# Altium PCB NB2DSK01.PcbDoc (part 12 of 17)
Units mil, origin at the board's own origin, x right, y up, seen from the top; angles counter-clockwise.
Board outline 11815 x 6500.03 mil, 8 copper layers (Top Layer, MidLayer1, MidLayer2, GND, PWR, MidLayer3, MidLayer4, Bottom Layer), stack 74.62 mil thick; 798 components, 1002 nets, 3927 pads, 3182 vias.
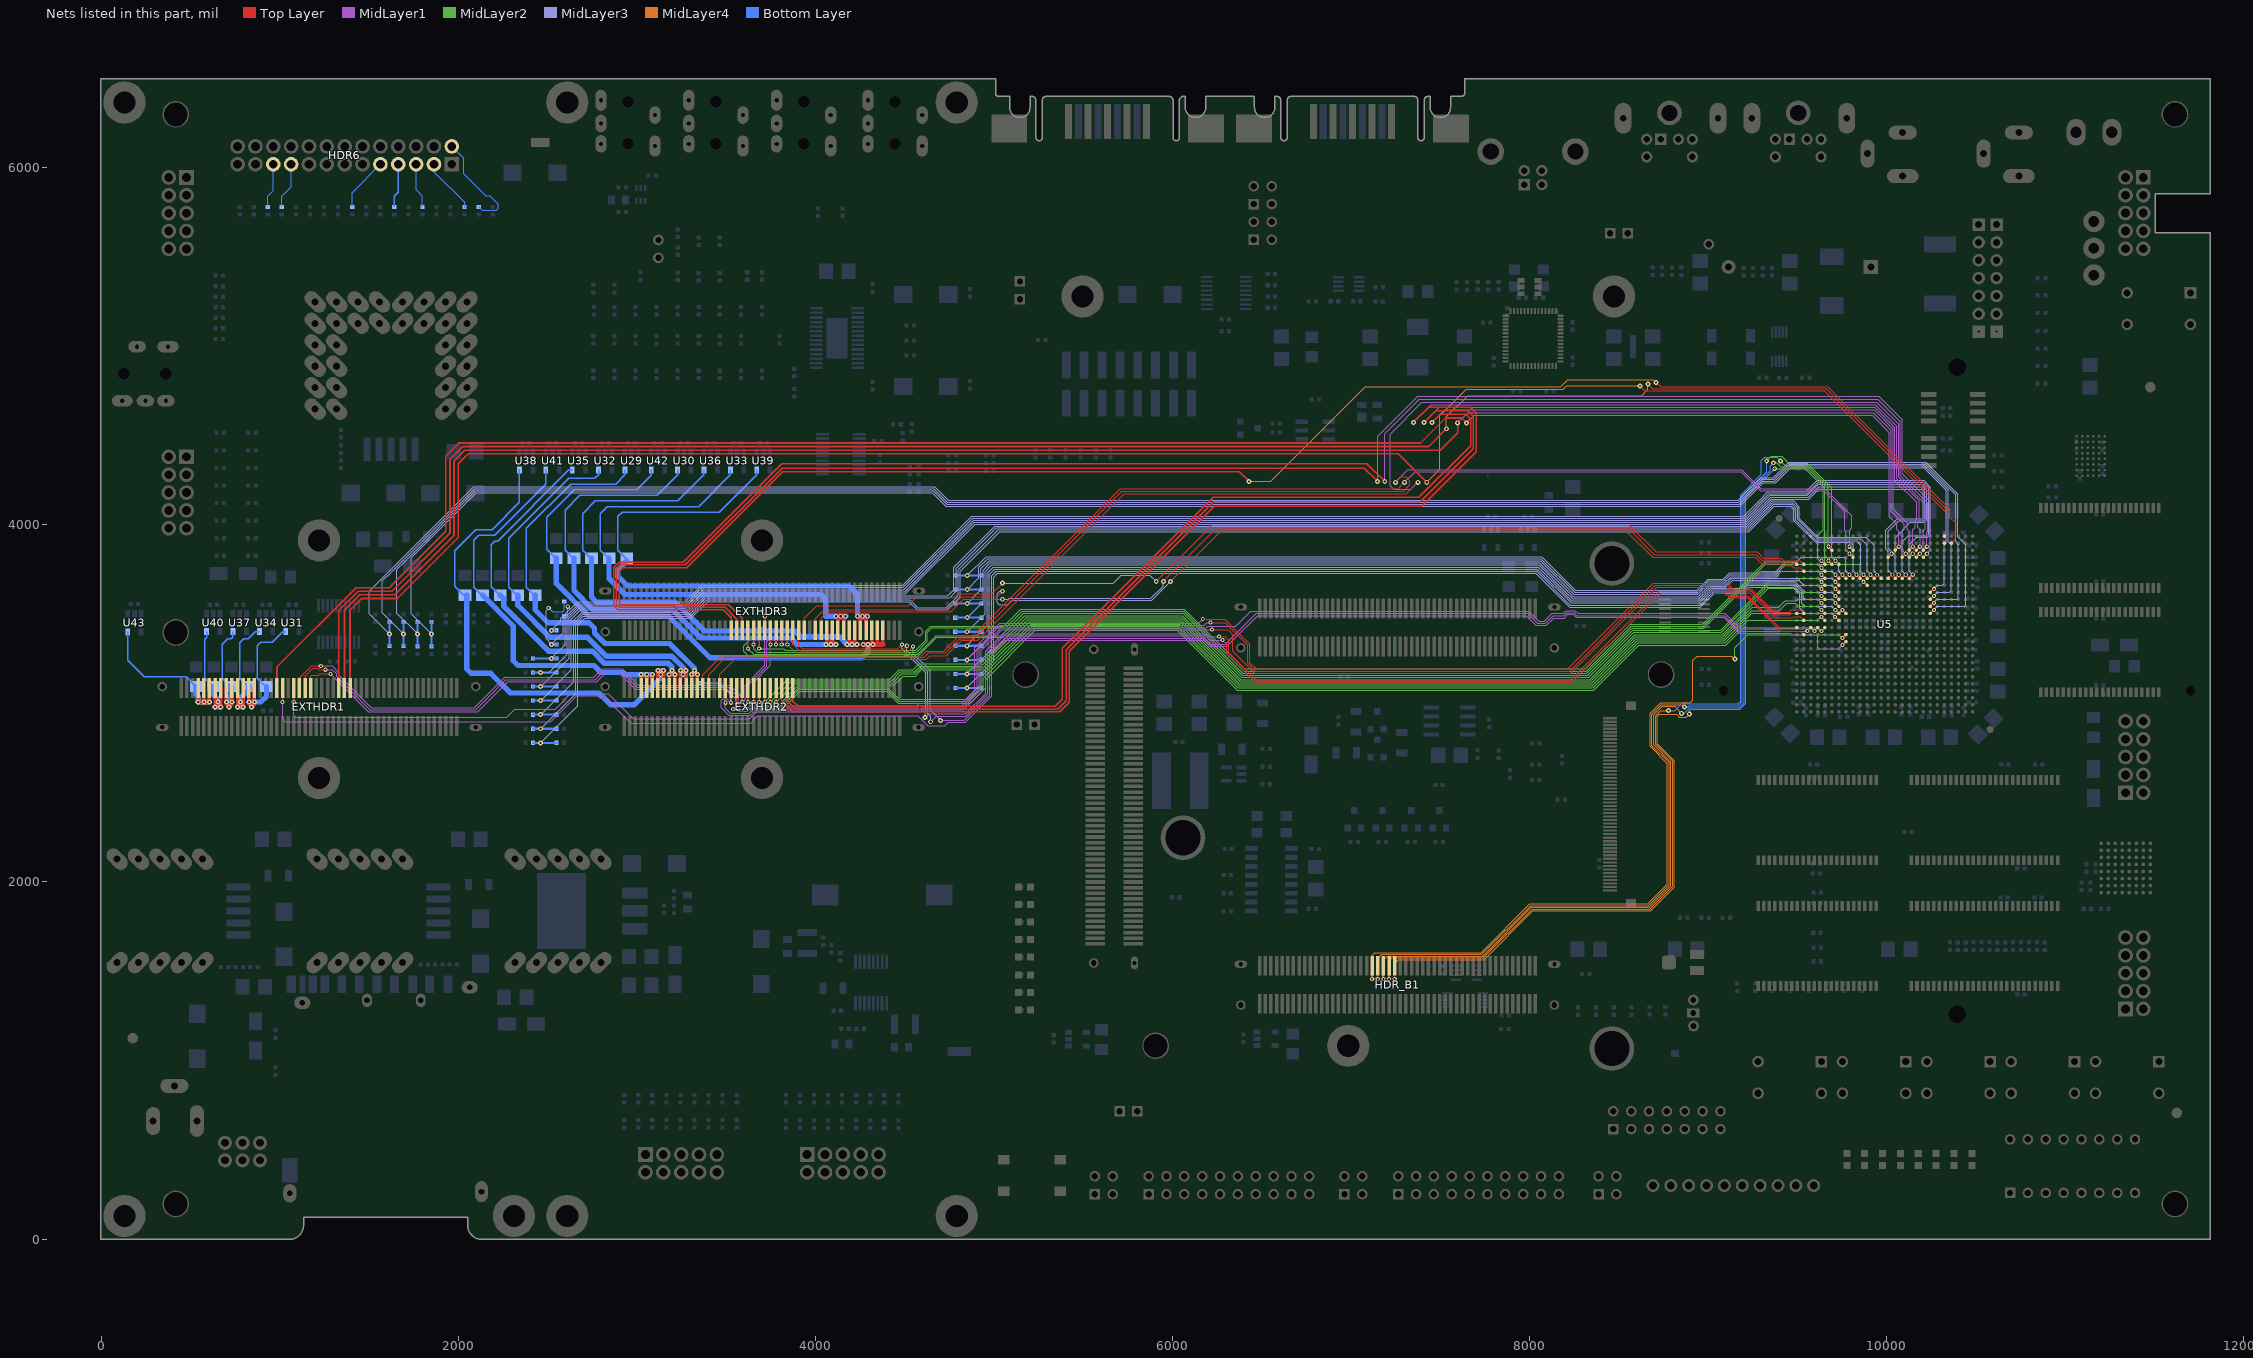
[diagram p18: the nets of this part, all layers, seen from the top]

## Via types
v1: diameter 23.62, hole 11.81, Top Layer to Bottom Layer, tented both sides, 1950 vias
v2: diameter 27.56, hole 11.81, Top Layer to Bottom Layer, tented both sides, 679 vias
v3: diameter 23.62, hole 11.81, Top Layer to Bottom Layer, 194 vias
v4: diameter 31.5, hole 11.81, Top Layer to Bottom Layer, tented both sides, 178 vias
v5: diameter 21.65, hole 11.81, Top Layer to Bottom Layer, tented both sides, 67 vias
v6: diameter 23.62, hole 11.81, Top Layer to Bottom Layer, tented bottom, 53 vias
v7: diameter 26, hole 11.81, Top Layer to Bottom Layer, tented both sides, 21 vias
v8: diameter 26, hole 11.81, Top Layer to Bottom Layer, 13 vias
v9: diameter 28, hole 11.81, Top Layer to Bottom Layer, 8 vias
v10: diameter 25.59, hole 11.81, Top Layer to Bottom Layer, tented both sides, 7 vias
v11: diameter 39.37, hole 11.81, Top Layer to Bottom Layer, tented both sides, 5 vias
v12: diameter 30, hole 11.81, Top Layer to Bottom Layer, 3 vias
v13: diameter 30, hole 11.81, Top Layer to Bottom Layer, tented both sides, 2 vias
v14: diameter 23, hole 11.81, Top Layer to Bottom Layer, tented both sides, 1 vias
v15: diameter 26.56, hole 11.81, Top Layer to Bottom Layer, tented both sides, 1 vias

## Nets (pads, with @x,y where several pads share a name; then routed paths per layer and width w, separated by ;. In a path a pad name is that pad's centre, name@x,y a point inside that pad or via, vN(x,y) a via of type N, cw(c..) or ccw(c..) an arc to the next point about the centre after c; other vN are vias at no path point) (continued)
PBCTRLA.JTAG.SOFT.TCK: R201.1 R205.1 U5.L20 | length 10456.2
  Top Layer w7.87: U5.L20@10244.09,3543.31 v1(10263.78,3562.99)
  MidLayer3 w5: v2(1692.91,3389.76) 1574.82,3507.86 1574.82,3685.85 1623.92,3734.95 2091.11,4202.14 4664,4202.14 4738.81,4127.34 9171.52,4127.34 9298.99,4254.8 9369.48,4254.8 9455.14,4340.45 10214.26,4340.45 10387,4167.72 10387,3904.34 10401.57,3889.76 10401.57,3590.55 10393.7,3582.68 10279.53,3582.68 v1(10263.78,3562.99)
  Bottom Layer w11.81: R205.1@1692.91,3322.36 R201.1@1692.91,3455.2
PBCTRLA.JTAG.SOFT.TDI: R198.1 R202.1 U5.J20 | length 10156.7
  Top Layer w7.87: U5.J20@10244.09,3622.05 v1(10264.57,3641.73)
  MidLayer3 w5: v2(1850.39,3387.8) 1736.75,3501.44 1736.75,3816.29 2100.33,4179.87 4654.78,4179.87 4729.58,4105.06 9177.53,4105.06 9307.27,4234.8 9377.77,4234.8 9463.42,4320.45 10205.98,4320.45 10333,4193.43 10333,3895.99 10322.83,3885.83 10322.83,3673.23 10311.02,3661.42 10283.47,3661.42 v1(10264.57,3641.73)
  Bottom Layer w11.81: R202.1@1850.39,3320.39 R198.1@1850.39,3455.2 R198.1@1850.39,3457.48
PBCTRLA.JTAG.SOFT.TDO: R199.1 R203.1 U5.K20 | length 10299.5
  Top Layer w7.87: U5.K20@10244.09,3582.68 v1(10264.57,3602.36)
  MidLayer3 w5: v2(1771.65,3389.76) 1655.59,3505.83 1655.59,3750.87 1699.07,3794.35 2095.72,4191 4659.39,4191 4734.19,4116.2 9174.53,4116.2 9303.13,4244.8 9373.63,4244.8 9459.28,4330.45 10210.12,4330.45 10343,4197.57 10343,3905.03 10362.2,3885.83 10362.2,3633.86 10350.39,3622.05 10283.47,3622.05 v1(10264.57,3602.36)
  Bottom Layer w11.81: R203.1@1771.65,3320.39 R199.1@1771.65,3455.2
PBCTRLA.JTAG.SOFT.TMS: R200.1 R204.1 U5.M20 | length 10602.6
  Top Layer w7.87: U5.M20@10244.09,3503.94 v1(10263.78,3523.62)
  MidLayer3 w5: v2(1614.17,3389.76) 1502.32,3501.62 1502.32,3628.06 1566.5,3692.24 2087.54,4213.27 4668.62,4213.27 4743.42,4138.47 9168.52,4138.47 9294.84,4264.8 9365.34,4264.8 9451,4350.45 10218.4,4350.45 10397,4171.86 10397,3933.71 10440.95,3889.76 10440.95,3551.18 10433.07,3543.31 10283.47,3543.31 v1(10263.78,3523.62)
  Bottom Layer w11.81: R204.1@1614.17,3322.36 R200.1@1614.17,3455.2
PBCTRLA.SPARE1: EXTHDR1.39 U5.A22 | length 10874.3
  Top Layer w5: v2(8617.38,4778.45) 8643.55,4752.28 9649.85,4752.28 9706.17,4695.97 10330.71,4071.43 10330.71,3964.57 10322.84,3956.69 U5.A22@10322.83,3937.01
  Top Layer w10: EXTHDR1.39@1393.7,3086.61 1393.7,3523.47 1458.68,3588.45 1659.32,3588.45 2000,3929.13 2000,4342.52 2055.93,4398.45 7263.68,4398.45 v2(7423.68,4238.45)
  MidLayer4 w5: v2(7423.68,4238.45) 7496.06,4310.84 7496.06,4610.24 7644.28,4758.45 8188.68,4758.45 8208.68,4778.45 v2(8617.38,4778.45)
PBCTRLA.SPARE2: EXTHDR1.41 U5.D16 | length 10635
  Top Layer w7.87: U5.D16@10086.61,3818.9 v1(10106.3,3838.58)
  Top Layer w10: EXTHDR1.41@1362.2,3086.61 1362.2,3521.98 1448.68,3608.45 1643.89,3608.45 1976.38,3940.94 1976.38,4358.27 2036.56,4418.45 7498.68,4418.45 7596.97,4516.74 v2(7596.97,4571.74)
  MidLayer1 w5: v2(7596.97,4571.74) 7653.68,4628.45 9923.68,4628.45 10025.33,4526.81 10025.33,4076.81 10098.43,4003.71 10098.43,3976.38 10086.62,3964.57 10086.62,3858.27 v1(10106.3,3838.58)
PBCTRLA.SPARE3: EXTHDR1.43 U5.B22 | length 10753.1
  Top Layer w5: v2(8662.38,4788.45) 8688.55,4762.28 9659.85,4762.28 9713.54,4708.59 10342.52,4079.61 10342.52,3917.32 U5.B22@10322.83,3897.64
  Top Layer w10: EXTHDR1.43@1330.71,3086.61 1330.71,3520.48 1438.68,3628.45 1628.45,3628.45 1952.76,3952.76 1952.76,4366.14 2025.07,4438.45 7433.68,4438.45 v2(7533.68,4538.45)
  MidLayer4 w5: v2(7533.68,4538.45) 7533.68,4604.55 7652.59,4723.45 8627.38,4723.45 8662.38,4758.45 v2(8662.38,4788.45)
PBCTRLA.SPARE4: EXTHDR1.65 U5.C15 | length 10729.9
  Top Layer w7.87: U5.C15@10047.24,3858.27 v1(10066.93,3877.95)
  Top Layer w10: EXTHDR1.65@984.25,3086.61 984.25,3204.02 1428.68,3648.45 1613.02,3648.45 1929.13,3964.57 1929.13,4385.83 2001.76,4458.45 7388.68,4458.45 7528.68,4598.45 7618.78,4598.45 v2(7646.23,4571)
  MidLayer1 w5: v2(7646.23,4571) 7688.68,4613.45 9918.68,4613.45 10015.27,4516.86 10015.27,4046.86 10055.12,4007.02 10055.12,3976.38 10066.93,3964.57 v1(10066.93,3877.95)
PBCTRLA.SPI_CS_N0: EXTHDR1.59 U5.N2 | length 9521.4
  Top Layer w5: v5(6220.47,3413.39) 6311.02,3413.39 6338.58,3385.83 6338.58,3291.34 6460.63,3169.29 8230.52,3169.29 8712.68,3651.45 9102.25,3651.45 9132.92,3620.79 9233.93,3620.79 9374.4,3480.32 9413.39,3480.32 9433.07,3480.32 9476.38,3480.32 9480.32,3484.25 9515.75,3484.25 U5.N2@9535.43,3464.57
  Top Layer w7.87: v1(1078.74,3007.87) EXTHDR1.59@1078.74,3086.61
  MidLayer1 w5: v1(1078.74,3007.87) 1078.74,2933.07 1090.55,2921.26 2270.37,2921.26 2315.54,2966.43 2541.65,2966.43 2642.16,3066.93 2795.28,3066.93 2807.09,3055.12 2838.58,3055.12 2980.32,2913.39 3632.25,2913.39 3671.62,2952.76 4590.55,2952.76 4602.36,2964.57 4830.71,2964.57 4929.13,3062.99 4929.13,3299.21 5043.31,3413.39 v5(6220.47,3413.39)
PBCTRLA.SPI_CS_N1: EXTHDR1.63 U5.T8 | length 9702.4
  Top Layer w7.87: v1(1015.75,3007.87) EXTHDR1.63@1015.75,3086.61 ; v1(9751.97,3326.77) U5.T8@9771.65,3346.46
  MidLayer1 w5: v1(1015.75,3007.87) 1015.75,2913.39 1031.5,2897.64 2516.59,2897.64 2662.26,3043.31 2779.53,3043.31 2791.34,3031.5 2822.83,3031.5 2964.57,2889.76 3636.91,2889.76 3678.1,2930.95 4572.99,2930.95 4629.92,2874.02 4724.41,2874.02 4744.09,2893.7 4838.58,2893.7 4988.19,3043.31 4988.19,3279.53 5062.99,3354.33 6177.17,3354.33 6212.6,3318.9 6303.15,3318.9 6342.52,3358.27 6476.39,3492.13 7980.31,3492.13 8035.43,3437.01 8092.46,3437.01 8133.91,3478.45 8193.68,3478.45 8213.68,3498.45 8243.68,3498.45 8260.01,3482.13 9085.68,3482.13 9174.11,3393.7 9413.39,3393.7 9433.07,3393.7 9460.63,3393.7 9468.5,3385.83 9602.36,3385.83 9614.17,3374.02 9614.17,3314.96 9622.05,3307.09 9732.28,3307.09 v1(9751.97,3326.77)
PBCTRLB.1W.ID: EXTHDR2.61 R143.1 U5.P4 | length 7088.1
  Top Layer w7.87: v1(3527.56,3004.42) EXTHDR2.61@3527.56,3086.61 ; v1(9594.49,3405.51) U5.P4@9614.17,3425.2
  MidLayer1 w5: v1(3527.56,3004.42) 3504.42,3027.56 3484.25,3027.56 3472.44,3015.75 3472.44,2976.38 3515.75,2933.07 3637.8,2933.07 3669.29,2964.57 4582.68,2964.57 4594.49,2976.38 4826.77,2976.38 4917.32,3066.93 4917.32,3303.15 5039.37,3425.2 6188.98,3425.2 6196.85,3433.07 6354.33,3433.07 6437.01,3515.75 7996.06,3515.75 8051.18,3460.63 8082.68,3460.63 8125.98,3503.94 8190.02,3503.94 8204.54,3518.45 8253.68,3518.45 8268.2,3503.94 9092.16,3503.94 9178.77,3417.32 9413.39,3417.32 9433.07,3417.32 9535.43,3417.32 9543.31,3425.2 9574.8,3425.2 v1(9594.49,3405.51)
  Bottom Layer w10: R143.1@3349.86,3113.45 3463.68,3113.45 3527.56,3049.58 v1(3527.56,3004.42)
PBCTRLB.1W.PIO1: EXTHDR2.69 U5.C9 | length 7463.6
  Top Layer w5: EXTHDR2.69@3401.57,3086.61 3401.57,3161.35 3498.68,3258.45 4608.68,3258.45 4633.68,3283.45 4728.68,3283.45 4808.68,3363.45 4890.68,3363.45 5715.68,4188.45 7293.68,4188.45 7328.68,4223.45 7328.68,4248.45 7308.68,4268.45 7278.68,4268.45 v2(7248.68,4238.45)
  Top Layer w7.87: v1(9791.34,3877.95) U5.C9@9811.02,3858.27
  MidLayer1 w5: v2(7248.68,4238.45) 7318.68,4308.45 9188.68,4308.45 9295.14,4202 9651.85,4202 9803.68,4050.17 9803.68,3983.45 9791.34,3971.11 v1(9791.34,3877.95)
PBCTRLB.1W.PIO2: EXTHDR2.71 U5.D9 | length 7308.5
  Top Layer w5: EXTHDR2.71@3370.08,3086.61 3370.08,3161.85 3476.68,3268.45 4596.68,3268.45 4621.68,3293.45 4718.68,3293.45 4798.68,3373.45 4876.68,3373.45 5706.68,4203.45 7263.68,4203.45 v2(7298.68,4238.45)
  Top Layer w7.87: v1(9791.34,3838.58) U5.D9@9811.02,3818.9
  MidLayer1 w5: v2(7298.68,4238.45) 7358.68,4298.45 9184.05,4298.45 9290.51,4192 9647.71,4192 9763.68,4076.03 9763.68,3968.45 9771.65,3960.48 9771.65,3858.27 v1(9791.34,3838.58)
PBCTRLB.CLK.CLK0: EXTHDR2.51 U5.M5 | length 6593.4
  Top Layer w7.87: v1(3685.04,3007.87) EXTHDR2.51@3685.04,3086.61 ; v1(9633.86,3523.62) U5.M5@9653.54,3503.94
  MidLayer2 w5: v1(3685.04,3007.87) 3704.72,2988.19 3791.34,2988.19 3901.58,3098.43 4437.01,3098.43 4492.13,3153.54 4559.78,3153.54 4594.09,3187.85 4947.7,3187.85 5204.72,3444.88 6039.37,3444.88 6374.02,3110.24 8345.27,3110.24 8597.24,3362.21 9086.61,3362.21 9108,3383.59 9244.86,3520.45 9398.41,3520.45 9438.86,3560.91 9486.34,3560.91 9503.94,3543.31 9614.17,3543.31 v1(9633.86,3523.62)
PBCTRLB.CLK.CLK1: EXTHDR2.45 U5.L5 | length 6484.4
  Top Layer w7.87: v1(3779.53,3007.87) EXTHDR2.45@3779.53,3086.61 ; v1(9633.86,3562.99) U5.L5@9653.54,3543.31
  MidLayer2 w5: v1(3779.53,3007.87) 3881.89,3110.24 4429.13,3110.24 4484.25,3165.36 4557.45,3165.36 4591.55,3199.45 4939.61,3199.45 5196.85,3456.69 6043.31,3456.69 6377.95,3122.05 8340.38,3122.05 8592.35,3374.02 9082.68,3374.02 9246.12,3537.45 9394.68,3537.45 9431.68,3574.45 9495.71,3574.45 9503.94,3582.68 9614.17,3582.68 v1(9633.86,3562.99)
PBCTRLB.CLK.CLK2: EXTHDR2.47 U5.K5 | length 6553.4
  Top Layer w7.87: v1(3748.03,3007.87) EXTHDR2.47@3748.03,3086.61 ; v1(9633.86,3602.36) U5.K5@9653.54,3582.68
  MidLayer2 w5: v1@3745.7,3007.87 v1@3746.87,3009.04 ; v1(3748.03,3007.87) 3862.21,3122.05 4421.26,3122.05 4476.38,3177.17 4555.12,3177.17 4587.41,3209.45 4929.93,3209.45 5188.98,3468.5 6047.24,3468.5 6381.89,3133.86 8335.49,3133.86 8587.45,3385.83 9077.78,3385.83 9337.63,3645.67 9417.32,3645.67 9433.07,3645.67 9488.19,3645.67 9511.81,3622.05 9614.17,3622.05 v1(9633.86,3602.36)
PBCTRLB.CLK.EN: EXTHDR2.49 U5.J5 | length 6580
  Top Layer w7.87: v1(3716.54,3007.87) EXTHDR2.49@3716.54,3086.61 ; v1(9633.86,3641.73) U5.J5@9653.54,3622.05
  MidLayer2 w5: v1(3716.54,3007.87) 3842.52,3133.86 4413.39,3133.86 4468.5,3188.98 4547.24,3188.98 4579.72,3221.45 4922.24,3221.45 5181.1,3480.32 6051.18,3480.32 6385.83,3145.67 8330.59,3145.67 8582.56,3397.64 9072.89,3397.64 9336.67,3661.42 9417.32,3661.42 9433.07,3661.42 9614.17,3661.42 v1(9633.86,3641.73)
PBCTRLB.JTAG.DETECT: R224.1 R225.1 U5.G9 | length 5394.3
  Top Layer w7.87: v1(9791.34,3720.47) U5.G9@9811.02,3700.79
  MidLayer3 w5: v2(4850.39,3716.54) 4956.69,3822.84 8066.93,3822.84 8255.91,3633.86 8938,3633.86 8999.99,3695.85 9084.86,3695.85 9119.8,3730.79 9372.34,3730.79 9431.08,3789.53 9490.32,3789.53 9519.69,3818.9 9759.84,3818.9 9771.65,3807.09 9771.65,3740.16 v1(9791.34,3720.47)
  Bottom Layer w11.81: R225.1@4782.99,3716.54 R224.1@4929.61,3716.54
PBCTRLB.JTAG.HARD.TCK: R211.1 R215.1 U5.L7 | length 5637.9
  Top Layer w7.87: v1(9712.6,3562.99) U5.L7@9732.28,3543.31
  MidLayer3 w5: v2(4848.43,3244.1) 4974.41,3370.08 4974.41,3722.44 5003.94,3751.97 8043.31,3751.97 8232.28,3562.99 8951.99,3562.99 9024.85,3635.85 9181.18,3635.85 9216.12,3670.79 9481.77,3670.79 9532.83,3619.73 9532.83,3593.16 9543.31,3582.68 9696.85,3582.68 v1(9712.6,3562.99)
  Bottom Layer w11.81: R215.1@4784.96,3244.1 R211.1@4929.61,3244.1
PBCTRLB.JTAG.HARD.TDI: R208.1 R212.1 U5.M7 | length 5727.6
  Top Layer w7.87: v1(9712.6,3523.62) U5.M7@9732.28,3503.94
  MidLayer3 w5: v2(4848.43,3165.36) 4986.22,3303.15 4986.22,3714.57 5011.81,3740.16 8039.37,3740.16 8228.35,3551.18 8954.32,3551.18 9028.99,3625.85 9187.89,3625.85 9222.83,3660.79 9477.63,3660.79 9522.83,3615.58 9522.83,3561.98 9541.5,3543.31 9692.91,3543.31 v1(9712.6,3523.62)
  Bottom Layer w11.81: R212.1@4784.96,3165.35 R208.1@4929.61,3165.35
PBCTRLB.JTAG.HARD.TDO: R209.1 R213.1 U5.N7 | length 5816.6
  Top Layer w7.87: v5@9709.84,3485.83 9710.84,3484.89 U5.N7@9732.28,3464.57
  MidLayer3 w5: v2(4848.43,3086.61) 4998.03,3236.22 4998.03,3706.69 5019.69,3728.35 8035.43,3728.35 8224.41,3539.37 8956.65,3539.37 9033.13,3615.85 9192.03,3615.85 9226.97,3650.79 9473.48,3650.79 9512.83,3611.44 9512.83,3534.41 9543.3,3503.94 9558.84,3503.94 9692.91,3503.94 v5@9709.84,3485.83
  Bottom Layer w11.81: R213.1@4784.96,3086.61 R209.1@4929.61,3086.61
  other v5: 9710.24,3484.25
PBCTRLB.JTAG.HARD.TMS: R210.1 R214.1 U5.K7 | length 5545.8
  Top Layer w7.87: v1(9712.6,3602.36) U5.K7@9732.28,3582.68
  MidLayer3 w5: v2(4848.43,3322.84) 4962.6,3437.01 4962.6,3730.32 4996.06,3763.78 8047.24,3763.78 8236.22,3574.8 8949.66,3574.8 9020.7,3645.85 9174.48,3645.85 9209.42,3680.79 9485.91,3680.79 9544.65,3622.05 9692.91,3622.05 v1(9712.6,3602.36)
  Bottom Layer w11.81: R214.1@4784.96,3322.84 R210.1@4929.61,3322.84
PBCTRLB.JTAG.SOFT.TCK: R219.1 R223.1 U5.G7 | length 5345.6
  Top Layer w7.87: v1(9712.6,3720.47) U5.G7@9732.28,3700.79
  MidLayer3 w5: v2(4850.39,3559.06) 4927.17,3635.83 4927.17,3753.94 4972.44,3799.21 8059.06,3799.21 8219.18,3639.09 8248.03,3610.24 8942.66,3610.24 9008.28,3675.85 9093.78,3675.85 9128.72,3710.79 9380.63,3710.79 9410,3740.16 9692.91,3740.16 v1(9712.6,3720.47)
  Bottom Layer w11.81: R223.1@4782.99,3559.06 R219.1@4929.61,3559.06
PBCTRLB.JTAG.SOFT.TDI: R216.1 R220.1 U5.J7 | length 5471.7
  Top Layer w7.87: v1(9712.6,3641.73) U5.J7@9732.28,3622.05
  MidLayer3 w5: v2@4850.39,3401.58 4950.79,3501.97 4950.79,3738.19 4988.19,3775.59 8051.18,3775.59 8206.07,3620.7 8240.16,3586.61 8947.32,3586.61 9016.56,3655.85 9102.06,3655.85 9137,3690.79 9506.07,3690.79 9535.43,3661.42 9692.91,3661.42 v1(9712.6,3641.73)
  Bottom Layer w11.81: R220.1@4782.99,3401.58 R216.1@4929.61,3401.58
  other v2: 4848.43,3401.58
PBCTRLB.JTAG.SOFT.TDO: R217.1 R221.1 U5.H7 | length 5396.5
  Top Layer w7.87: v1(9712.6,3681.1) U5.H7@9732.28,3661.42
  MidLayer3 w5: v2(4850.39,3480.32) 4938.98,3568.9 4938.98,3746.06 4980.32,3787.4 8055.12,3787.4 8244.09,3598.43 8944.99,3598.43 9012.42,3665.85 9097.92,3665.85 9132.86,3700.79 9433.07,3700.79 9692.91,3700.79 v1(9712.6,3681.1)
  Bottom Layer w11.81: R221.1@4782.99,3480.32 R217.1@4929.61,3480.32
PBCTRLB.JTAG.SOFT.TMS: R218.1 R222.1 U5.G8 | length 5366.5
  Top Layer w7.87: v1(9751.97,3720.47) U5.G8@9771.65,3700.79
  MidLayer3 w5: v2(4850.39,3637.8) 4915.35,3702.76 4915.35,3761.81 4964.57,3811.02 8062.99,3811.02 8251.97,3622.05 8940.33,3622.05 9004.13,3685.85 9089,3685.85 9123.94,3720.79 9376.49,3720.79 9435.23,3779.53 9720.47,3779.53 9732.28,3767.72 9732.28,3740.16 v1(9751.97,3720.47)
  Bottom Layer w11.81: R222.1@4782.99,3637.8 R218.1@4929.61,3637.8
PBCTRLB.SPARE1: EXTHDR2.39 U5.D17 | length 8472.6
  Top Layer w7.87: U5.D17@10125.98,3818.9 v1(10145.67,3838.58)
  Top Layer w8: EXTHDR2.39@3874.02,3086.61 3874.02,3013.12 3903.68,2983.45 5342.68,2983.45 5383.68,3024.45 5383.68,3308.45 6228.68,4153.45 7378.68,4153.45 7669.29,4444.06 7669.29,4592.84 7643.68,4618.45 7498.68,4618.45 v2(7453.68,4573.45)
  MidLayer1 w5: v2(7453.68,4573.45) 7523.68,4643.45 9928.68,4643.45 10035.74,4536.39 10035.74,4086.39 10114.17,4007.96 10114.17,3976.38 10125.99,3964.57 10125.99,3858.27 v1(10145.67,3838.58)
PBCTRLB.SPARE2: EXTHDR2.41 U5.C17 | length 8674.6
  Top Layer w7.87: U5.C17@10125.98,3858.27 v1(10145.67,3877.95)
  Top Layer w8: EXTHDR2.41@3842.52,3086.61 3842.52,3014.61 3888.68,2968.45 5356.68,2968.45 5403.68,3015.45 5403.68,3300.45 6231.68,4128.45 7386.68,4128.45 7685.04,4426.81 7685.04,4607.1 7653.68,4638.45 7473.68,4638.45 v2(7408.68,4573.45)
  MidLayer1 w5: v2(7408.68,4573.45) 7493.68,4658.45 9931.68,4658.45 10045.74,4544.39 10045.74,4247.39 10167.68,4125.45 10167.68,4033.45 10159.68,4025.45 10159.68,3986.45 10145.67,3972.44 v1(10145.67,3877.95)
PBCTRLB.SPARE3: EXTHDR2.43 U5.C18 | length 8936.3
  Top Layer w7.87: U5.C18@10165.35,3858.27 v1(10185.04,3877.95)
  Top Layer w8: EXTHDR2.43@3811.02,3086.61 3811.02,3016.11 3873.68,2953.45 5369.68,2953.45 5421.68,3005.45 5421.68,3291.45 6233.68,4103.45 7395.68,4103.45 7700.79,4408.56 7700.79,4626.35 7668.68,4658.45 7433.68,4658.45 v2(7348.68,4573.45)
  MidLayer1 w5: v2(7348.68,4573.45) 7447.68,4672.45 9936.68,4672.45 10055.74,4553.39 10055.74,4259.39 10180.68,4134.45 10180.68,4022.45 10174.68,4016.45 10174.68,3987.45 10187.68,3974.45 10187.68,3880.6 v1(10185.04,3877.95)
PBCTRLB.SPARE4: EXTHDR2.65 U5.D18 | length 8699.6
  Top Layer w5: EXTHDR2.65@3464.57,3086.61 3464.57,3162.34 3548.68,3246.45 4621.68,3246.45 4643.68,3268.45 4733.68,3268.45 4818.68,3353.45 4908.68,3353.45 5728.68,4173.45 7308.68,4173.45 v2(7373.68,4238.45)
  Top Layer w7.87: U5.D18@10165.35,3818.9 v1(10185.04,3838.58)
  MidLayer1 w5: v2(7373.68,4238.45) 7333.68,4198.45 7238.68,4198.45 7218.68,4218.45 7218.68,4508.45 7396.68,4686.45 9942.68,4686.45 10065.74,4563.39 10065.74,4265.39 10215.68,4115.45 10215.68,3977.45 10204.68,3966.45 10204.68,3858.23 v1(10185.04,3838.58)
PBCTRLB.SPI_CS_N0: EXTHDR2.59 U5.M2 | length 6934
  Top Layer w5: v5(6169.29,3472.44) 6291.34,3472.44 6433.07,3330.71 6433.07,3228.35 6468.5,3192.91 8212.48,3192.91 8693.02,3673.45 9108.53,3673.45 9141.2,3640.79 9242.21,3640.79 9371.19,3511.81 9456.69,3511.81 9468.5,3523.62 9515.75,3523.62 U5.M2@9535.43,3503.94
  Top Layer w7.87: v1(3539.37,2968.5) 3559.06,2988.19 EXTHDR2.59@3559.06,3086.61
  MidLayer1 w5: v1(3539.37,2968.5) 3559.06,2968.5 3570.87,2956.69 3622.05,2956.69 3653.54,2988.19 4566.93,2988.19 4578.74,3000 4818.9,3000 4893.7,3074.8 4893.7,3311.02 5031.5,3448.82 6145.67,3448.82 v5(6169.29,3472.44)
PBCTRLB.SPI_CS_N1: EXTHDR2.63 U5.M1 | length 6918.4
  Top Layer w5: v5(6212.6,3452.76) 6295.28,3452.76 6421.26,3326.77 6421.26,3224.41 6464.57,3181.1 8223.33,3181.1 8704.68,3662.45 9105.39,3662.45 9137.06,3630.79 9238.07,3630.79 9372.79,3496.06 9413.39,3496.06 9433.07,3496.06 9460.63,3496.06 9468.5,3503.94 U5.M1@9496.06,3503.94
  Top Layer w7.87: v1(3496.06,3004.42) EXTHDR2.63@3496.06,3086.61
  MidLayer1 w5: v1(3496.06,3004.42) 3496.06,2972.44 3523.62,2944.88 3629.92,2944.88 3661.42,2976.38 4570.87,2976.38 4582.68,2988.19 4822.83,2988.19 4905.51,3070.87 4905.51,3307.09 5035.43,3437.01 6177.17,3437.01 6192.91,3452.76 v5(6212.6,3452.76)
PBCTRLC.1W.ID: EXTHDR3.61 R144.1 U5.R2 | length 6959.3
  Top Layer w5: EXTHDR3.61@3874.02,3388.45 3874.02,3330.71 ; 3896.43,3308.29 3874.02,3330.71 ; v1(4511.81,3322.84) 4484.25,3295.28 3909.45,3295.28 3874.02,3330.71 ; v5(6279.53,3354.33) 6303.15,3330.71 6303.15,3279.53 6463.22,3119.45 8236.68,3119.45 8716.67,3599.44 8735.68,3618.45 9092.82,3618.45 9120.49,3590.79 9221.5,3590.79 9406.78,3405.51 9515.75,3405.51 U5.R2@9535.43,3385.83
  MidLayer1 w5: v2(4645.67,2897.64) 4677.17,2929.13 4842.52,2929.13 4964.57,3051.18 4964.57,3287.4 5055.12,3377.95 6185.04,3377.95 6208.66,3354.33 v5(6279.53,3354.33)
  MidLayer3 w5: v1(4511.81,3322.84) 4511.81,3295.28 4629.92,3177.17 4629.92,2940.95 4645.67,2925.2 v2(4645.67,2897.64)
  Bottom Layer w5: R144.1@4511.81,3264.66 v1(4511.81,3322.84)
PBCTRLC.1W.PIO1: EXTHDR3.69 U5.F2 | length 6051.2
  Top Layer w5: EXTHDR3.69@4000,3409.45 4000,3474.77 4048.68,3523.45 4743.68,3523.45 4818.68,3598.45 5018.68,3598.45 v2(5048.68,3628.45) ; v2(5988.68,3683.45) 6273.68,3968.45 8538.68,3968.45 8688.68,3818.45 9263.68,3818.45 9298.68,3783.45 9398.68,3783.45 9410.48,3771.65 9464.57,3771.65 9476.38,3759.84 9515.75,3759.84 U5.F2@9535.43,3740.16
  MidLayer3 w5: v2(5048.68,3628.45) 5033.68,3628.45 5018.68,3613.45 5018.68,3563.45 5028.68,3553.45 5076,3553.45 5100.55,3578 5883.23,3578 v2(5988.68,3683.45)
PBCTRLC.1W.PIO2: EXTHDR3.71 U5.E1 | length 5841.1
  Top Layer w5: EXTHDR3.71@4031.5,3409.45 4031.5,3476.27 4068.68,3513.45 4758.68,3513.45 4828.68,3583.45 v2(5048.68,3583.45) ; v2(5948.68,3683.45) 6248.68,3983.45 8548.68,3983.45 8698.68,3833.45 9268.68,3833.45 9303.68,3798.45 9403.68,3798.45 9414.73,3787.4 9468.5,3787.4 9476.38,3779.53 U5.E1@9496.06,3779.53
  MidLayer3 w5: v2(5048.68,3583.45) 5080.45,3583.45 5085,3588 5879.09,3588 5948.68,3657.6 v2(5948.68,3683.45)
PBCTRLC.CLK.CLK0: EXTHDR3.51 U5.H5 | length 6865.6
  Top Layer w7.87: EXTHDR3.51@3716.54,3409.45 v1(3716.54,3488.19) ; v1(9633.86,3681.1) U5.H5@9653.54,3661.42
  MidLayer2 w5: v1(3716.54,3488.19) 3716.54,3440.95 3598.43,3322.84 3598.43,3291.34 3625.98,3263.78 4574.2,3263.78 4680.42,3370 5051.1,3370 5173.23,3492.13 6055.12,3492.13 6389.76,3157.48 8325.7,3157.48 8577.67,3409.45 9070.56,3409.45 9347.57,3686.45 9503.05,3686.45 9517.39,3700.79 9614.17,3700.79 v1(9633.86,3681.1)
PBCTRLC.CLK.CLK1: EXTHDR3.45 U5.G5 | length 6632.9
  Top Layer w7.87: v1(3622.05,3307.09) EXTHDR3.45@3622.05,3409.45 ; v1(9633.86,3720.47) U5.G5@9653.54,3700.79
  MidLayer2 w5: v1(3622.05,3307.09) 3653.54,3275.59 4571.87,3275.59 4676.28,3380 5041.42,3380 5165.35,3503.94 6059.06,3503.94 6393.7,3169.29 8320.81,3169.29 8572.78,3421.26 8974.49,3421.26 9293.39,3740.16 9614.17,3740.16 v1(9633.86,3720.47)
PBCTRLC.CLK.CLK2: EXTHDR3.47 U5.F5 | length 6637.7
  Top Layer w7.87: v1(3653.54,3330.71) EXTHDR3.47@3653.54,3409.45 ; v1(9633.86,3759.84) U5.F5@9653.54,3740.16
  MidLayer2 w5: v1(3653.54,3330.71) 3653.54,3307.09 3673.23,3287.4 4566.63,3287.4 4627.68,3348.45 4627.68,3399.31 4651.37,3423 5064.73,3423 5157.48,3515.75 6062.99,3515.75 6397.64,3181.1 8315.92,3181.1 8567.88,3433.07 8972.16,3433.07 9318.61,3779.53 9417.32,3779.53 9433.07,3779.53 9614.17,3779.53 v1(9633.86,3759.84)
PBCTRLC.CLK.EN: EXTHDR3.49 U5.E5 | length 6612
  Top Layer w7.87: v1(3685.04,3307.09) EXTHDR3.49@3685.04,3409.45 ; v1(9633.86,3799.21) U5.E5@9653.54,3779.53
  MidLayer2 w5: v1(3685.04,3307.09) 3822.84,3307.09 3830.71,3299.21 4562.99,3299.21 4617.68,3353.9 4617.68,3403.45 4647.23,3433 5055.05,3433 5096.54,3474.49 5149.61,3527.56 6066.93,3527.56 6401.57,3192.91 8311.02,3192.91 8562.99,3444.88 8969.83,3444.88 9318.4,3793.45 9495.17,3793.45 9520.62,3818.9 9604,3818.9 9623.68,3799.21 v1(9633.86,3799.21)
PBCTRLC.JTAG.DETECT: R242.1 R243.1 U5.G10 | length 8748.3
  Top Layer w7.87: v1(9830.71,3720.47) U5.G10@9850.39,3700.79
  MidLayer3 w5: v2(2460.63,2779.53) 2669.29,2988.19 2669.29,3437.01 2708.66,3476.38 3303.15,3476.38 3397.32,3570.55 4523.74,3570.55 4570.67,3523.62 4736.22,3523.62 4811.02,3598.43 4811.02,3739.83 5031.5,3960.3 9226.26,3960.3 9370.76,4104.8 9462.7,4104.8 9480.3,4087.2 9480.3,4022.4 9601.12,3901.58 9795.28,3901.58 9811.02,3885.83 9811.02,3740.16 v1(9830.71,3720.47)
  Bottom Layer w11.81: R242.1@2418.43,2779.53 R243.1@2548.9,2779.53 R243.1@2552.76,2779.53
PBCTRLC.JTAG.HARD.TCK: R229.1 R233.1 U5.G15 | length 8973
  Top Layer w7.87: U5.G15@10047.24,3700.79 v1(10066.93,3720.47)
  MidLayer3 w5: v2(2521.65,3251.97) 2598.43,3328.74 2598.43,3468.5 2677.17,3547.24 3279.53,3547.24 3370.08,3637.8 4496.06,3637.8 4885.38,4027.12 9208.22,4027.12 9345.9,4164.8 9555.65,4164.8 9617.31,4226.45 10200.98,4226.45 10224,4203.44 10224,4029 10209,4014 10132,4014 10047.18,3929.18 10047.18,3740.22 v1(10066.93,3720.47)
  Bottom Layer w11.81: R229.1@2418.43,3251.97 R233.1@2550.87,3251.97 R233.1@2556.69,3251.97
PBCTRLC.JTAG.HARD.TDI: R226.1 R230.1 U5.G16 | length 9191.9
  Top Layer w7.87: U5.G16@10086.61,3700.79 v1(10106.3,3720.47)
  MidLayer3 w5: v1(2506,3535) 2491.26,3520.26 2491.26,3361.1 v2(2521.65,3330.71) 2586.61,3395.67 2586.61,3472.44 2673.23,3559.06 3275.59,3559.06 3366.14,3649.61 4492.13,3649.61 4880.77,4038.25 9203.61,4038.25 9340.15,4174.8 9551.51,4174.8 9615.16,4238.45 10203.12,4238.45 10234,4207.58 10234,3951.71 10221.86,3939.57 10120.67,3939.57 10086.61,3905.51 10086.61,3740.16 v1(10106.3,3720.47)
  Bottom Layer w5: v1(2506,3535) 2528.1,3512.9 2584.25,3512.9 2593.23,3521.89 R226.1@2593.23,3566.93
  Bottom Layer w11.81: v2(2521.65,3330.71) R230.1@2550.87,3330.71 R230.1@2555.91,3330.71
PBCTRLC.JTAG.HARD.TDO: R227.1 R231.1 U5.G17 | length 8825.4
  Top Layer w7.87: U5.G17@10125.98,3700.79 v1(10145.67,3721.26)
  MidLayer3 w5: v2(2521.65,3409.45) 2574.8,3462.6 2574.8,3476.38 2669.29,3570.87 3271.65,3570.87 3362.2,3661.42 4488.19,3661.42 4876.16,4049.39 9198.99,4049.39 9290.66,4141.06 9334.41,4184.8 9547.37,4184.8 9612.02,4249.45 10206.27,4249.45 10244,4211.72 10244,3947.57 10226,3929.57 10167.55,3929.57 10125.98,3888 10125.98,3740.16 v1(10145.67,3721.26) ; v1(2613,3542) 2626.67,3528.33
  Bottom Layer w5: v2(2521.65,3409.45) R231.1@2550.87,3409.45 ; R227.1@2593.23,3488.19 2611.19,3488.19 2613,3490 v1(2613,3542)
PBCTRLC.JTAG.HARD.TMS: R228.1 R232.1 U5.D14 | length 9008.6
  Top Layer w7.87: U5.D14@10007.87,3818.9 v1(10027.56,3838.58)
  MidLayer3 w5: v2@2450.79,3173.23 2507.87,3173.23 2610.24,3275.59 2610.24,3464.57 2681.1,3535.43 3283.46,3535.43 3374.02,3625.98 4500,3625.98 4889.76,4015.75 ; 4889.76,4015.98 9211.22,4015.98 9350.04,4154.8 9559.8,4154.8 9618.45,4213.45 10199.84,4213.45 10214,4199.29 10214,4033.14 10204.86,4024 10067.18,4024 10007.68,3964.5 10007.68,3869.27 10027.56,3849.39 v1(10027.56,3838.58)
  Bottom Layer w11.81: R228.1@2418.43,3173.23 R232.1@2550.87,3173.23 R232.1@2553.54,3173.23
  other v2: 2460.63,3173.23
PBCTRLC.JTAG.SOFT.TCK: R237.1 R241.1 U5.G12 | length 8657.4
  Top Layer w7.87: v1(9909.45,3720.47) U5.G12@9929.13,3700.79
  MidLayer3 w5: v2(2460.63,2937.01) 2645.67,3122.05 2645.67,3448.82 2696.85,3500 3295.28,3500 3385.83,3590.55 4751.97,3590.55 4789.21,3627.8 4789.21,3757.72 5014.07,3982.57 9220.24,3982.57 9362.47,4124.8 9470.98,4124.8 9500.3,4095.48 9500.3,4030.68 9609.41,3921.58 9854.01,3921.58 9889.76,3885.83 9889.76,3740.16 v1(9909.45,3720.47)
  Bottom Layer w11.81: R237.1@2418.43,2937.01 R241.1@2548.9,2937.01
PBCTRLC.JTAG.SOFT.TDI: R234.1 R238.1 U5.G14 | length 9142.5
  Top Layer w7.87: U5.G14@10007.87,3700.79 v5@10027.56,3720.47
  MidLayer3 w5: v2@2462.6,3094.49 2622.05,3253.94 2622.05,3460.63 2685.04,3523.62 3287.4,3523.62 3377.95,3614.17 4503.94,3614.17 4894.61,4004.85 9214.23,4004.85 9354.19,4144.8 9563.94,4144.8 9619.59,4200.45 10198.7,4200.45 10204,4195.15 10204,4037.28 10200.72,4034 10059.32,4034 9994.68,3969.36 9994.68,3866.45 10007.6,3853.53 10007.6,3744.37 v5(10031.5,3720.47)
  Bottom Layer w11.81: R234.1@2418.43,3094.49 R238.1@2550.87,3094.49
  other v2: 2460.63,3094.49
PBCTRLC.JTAG.SOFT.TDO: R235.1 R239.1 U5.G13 | length 8635.2
  Top Layer w7.87: v5@9948.82,3720.47 U5.G13@9968.5,3700.79
  MidLayer3 w5: v2(2460.63,3015.75) 2633.86,3188.98 2633.86,3452.76 2692.91,3511.81 3291.34,3511.81 3381.89,3602.36 4740.16,3602.36 4775.59,3637.8 4775.59,3763.78 5005.52,3993.71 9217.24,3993.71 9358.33,4134.8 9475.13,4134.8 9510.3,4099.63 9510.3,4034.83 9613.55,3931.58 9883.39,3931.58 9929.13,3885.83 9929.13,3740.16 v5@9948.82,3720.47
  Bottom Layer w11.81: R235.1@2418.43,3015.75 R239.1@2550.87,3015.75
  other v5: 9944.88,3720.47
PBCTRLC.JTAG.SOFT.TMS: R236.1 R240.1 U5.G11 | length 8729.5
  Top Layer w7.87: v1(9870.08,3720.47) U5.G11@9889.76,3700.79
  MidLayer3 w5: v2(2460.63,2858.27) 2657.48,3055.12 2657.48,3444.88 2700.79,3488.19 3299.21,3488.19 3391.57,3580.55 4527.88,3580.55 4573,3535.43 4732.28,3535.43 4799.21,3602.36 4799.21,3748.03 5022.62,3971.44 9223.25,3971.44 9366.61,4114.8 9466.84,4114.8 9490.3,4091.34 9490.3,4026.54 9605.27,3911.58 9828.58,3911.58 9850.39,3889.76 9850.39,3736.22 v1(9870.08,3720.47)
  Bottom Layer w11.81: R236.1@2418.43,2858.27 R240.1@2548.9,2858.27
PBCTRLC.SPARE1: EXTHDR3.39 U5.C19 | length 9647.6
  Top Layer w7.87: U5.C19@10204.72,3858.27 v1(10224.41,3877.95)
  Top Layer w8: EXTHDR3.39@3527.56,3409.45 3527.56,3479.58 3483.68,3523.45 2893.87,3523.45 2870.08,3547.24 2870.08,3759.84 2901.57,3791.34 3259.84,3791.34 3811.96,4343.45 7088.68,4343.45 v2(7188.68,4243.45)
  MidLayer1 w5: v2(7188.68,4243.45) 7188.68,4509.68 7382.45,4703.45 9948.68,4703.45 10075.74,4576.39 10075.74,4274.39 10228.68,4121.45 10228.68,3964.45 10224.41,3960.18 v1(10224.41,3877.95)
PBCTRLC.SPARE2: EXTHDR3.41 U5.D19 | length 9683.7
  Top Layer w7.87: U5.D19@10204.72,3818.9 v1(10224.41,3838.58)
  Top Layer w8: EXTHDR3.41@3559.06,3409.45 3559.06,3474.16 3557.97,3474.16 3493.68,3538.45 2902.49,3538.45 2885.83,3555.12 2885.83,3748.03 2913.39,3775.59 3271.65,3775.59 3814.52,4318.45 7073.68,4318.45 v2(7148.68,4243.45)
  MidLayer1 w5: v2(7148.68,4243.45) 7148.68,4495.68 7373.45,4720.45 9954.68,4720.45 10087.68,4587.45 10087.68,4286.45 10244.09,4130.04 10244.09,3858.27 v1(10224.41,3838.58)
PBCTRLC.SPARE3: EXTHDR3.43 U5.B23 | length 9427.9
  Top Layer w5: v2(8707.38,4798.45) 8733.55,4772.28 9669.85,4772.28 10353.68,4088.45 10353.68,4043.45 10388.68,4008.45 10388.68,3963.48 10383.08,3957.89 10383.08,3918.52 U5.B23@10362.2,3897.64
  Top Layer w8: EXTHDR3.43@3590.55,3409.45 3590.55,3476.58 3513.68,3553.45 2911.11,3553.45 2901.57,3562.99 2901.57,3740.16 2921.26,3759.84 3279.53,3759.84 3818.14,4298.45 6373.68,4298.45 v2(6428.68,4243.45)
  MidLayer4 w5: v2(6428.68,4243.45) 6549.45,4243.45 7079.45,4773.45 8173.68,4773.45 8213.68,4813.45 8692.38,4813.45 v2(8707.38,4798.45)
PBCTRLC.SPARE4: EXTHDR3.65 U5.E2 | length 6001.4
  Top Layer w5: EXTHDR3.65@3937.01,3409.45 3937.01,3476.78 4008.68,3548.45 4518.68,3548.45 4563.68,3593.45 4778.68,3593.45 4798.68,3613.45 4988.68,3613.45 v2(5048.68,3673.45) ; v2(5908.68,3683.45) 6223.68,3998.45 8558.68,3998.45 8708.68,3848.45 9273.68,3848.45 9308.68,3813.45 9408.68,3813.45 9422.94,3799.2 9515.76,3799.2 U5.E2@9535.43,3779.53
  MidLayer3 w5: v2(5048.68,3673.45) 5669,3673.45 5713.89,3718.35 5873.79,3718.35 v2(5908.68,3683.45)
PBCTRLC.SPI_CS_N0: EXTHDR3.59 U5.P3 | length 6682.6
  Top Layer w5: v1(3842.52,3330.71) 3889.76,3283.47 4511.81,3283.47 v1(4547.24,3318.9)
  Top Layer w7.87: v1(3842.52,3330.71) EXTHDR3.59@3842.52,3409.45 ; v1(9555.12,3405.51) U5.P3@9574.8,3425.2
  MidLayer1 w5: v2(4700.79,2905.51) 4834.65,2905.51 4976.38,3047.24 4976.38,3283.47 5059.06,3366.14 6181.1,3366.14 6216.54,3330.71 6295.28,3330.71 6468.5,3503.94 7988.19,3503.94 8043.31,3448.82 8087.57,3448.82 8130.88,3492.13 8192.35,3492.13 8208.68,3508.45 8248.68,3508.45 8265.01,3492.13 9089.83,3492.13 9176.44,3405.51 9413.39,3405.51 9433.07,3405.51 v1(9555.12,3405.51)
  MidLayer3 w5: v1(4547.24,3318.9) 4547.24,3279.53 4641.73,3185.04 4641.73,2964.57 v2(4700.79,2905.51)
PBCTRLC.SPI_CS_N1: EXTHDR3.63 U5.P1 | length 6797.9
  Top Layer w5: EXTHDR3.63@3905.51,3409.45 3905.51,3326.77 3925.2,3307.09 4460.63,3307.09 v1(4484.25,3330.71) ; v5(6259.84,3374.02) 6295.28,3374.02 6314.96,3354.33 6314.96,3283.47 6465.97,3132.45 8230.68,3132.45 8726.68,3628.45 9096.97,3628.45 9124.63,3600.79 9225.64,3600.79 9401.23,3425.2 U5.P1@9496.06,3425.2
  MidLayer1 w5: v2(4614.17,2921.26) 4633.86,2940.95 4838.58,2940.95 4952.76,3055.12 4952.76,3291.34 5051.18,3389.76 6188.98,3389.76 6204.72,3374.02 v5(6259.84,3374.02)
  MidLayer3 w5: v1(4484.25,3330.71) 4484.25,3307.09 4618.11,3173.23 4618.11,2952.76 4614.17,2948.82 v2(4614.17,2921.26)
PBPOWER.1V2PBA: EXTHDR1.73 EXTHDR1.75 R164.2 U31.5 | length 922.9
  Top Layer w19.68: EXTHDR1.75@826.77,3086.61 v2(826.77,3007.87) ; EXTHDR1.73@858.27,3086.61 v2(858.27,3007.87) ; v2@826.77,2996.06 v2(826.77,3007.87) ; v2@826.77,2996.06 v2(842.52,2980.32) v2@858.27,2996.06 ; v2@826.77,2996.06 842.52,2996.06 v2@858.27,2996.06 ; v2(826.77,3007.87) v2(858.27,3007.87) ; v2@858.27,2996.06 v2(858.27,3007.87)
  Bottom Layer w7.87: R164.2@921.26,3094.49 874.02,3141.73 874.02,3322.83 893.7,3342.52 956.69,3342.52 1016.11,3401.94 U31.5@1033.46,3401.94
  Bottom Layer w29.53: v2(826.77,3007.87) 842.52,3007.87 ; v2(842.52,2980.32) 842.52,3007.87 ; R164.2@925.2,3094.49 925.2,3039.37 893.7,3007.87 v2(858.27,3007.87) 842.52,3007.87
PBPOWER.1V2PBB: EXTHDR2.73 EXTHDR2.75 R162.2 U29.5 | length 2486.4
  Top Layer w19.68: EXTHDR2.75@3307.09,3086.61 v2(3307.09,3161.42) ; EXTHDR2.73@3338.58,3078.74 EXTHDR2.73@3338.58,3086.61 v2(3338.58,3161.42) ; v2(3307.09,3161.42) 3307.09,3169.29 v2(3322.83,3185.04) 3338.58,3169.29 v2(3338.58,3161.42) ; v2(3307.09,3161.42) v2(3338.58,3161.42)
  Bottom Layer w7.87: R162.2@2429.13,3602.36 2428.15,3603.35 2381.89,3649.61 2381.89,3980.32 2629.92,4228.35 2881.89,4228.35 2933.07,4279.53 U29.5@2933.07,4307.45
  Bottom Layer w29.53: R162.2@2431.1,3606.3 2431.1,3524 2503.1,3452 2732,3452 2763,3421 2763,3395 2822,3336 3183.69,3336 3322.83,3196.85 v2(3322.83,3185.04)
PBPOWER.1V2PBC: EXTHDR3.73 EXTHDR3.75 R163.2 U30.5 | length 3063.8
  Top Layer w19.68: v2(4059.06,3330.71) v2(4086.61,3330.71) v2(4114.17,3330.71) 4100.39,3344.49 4094.49,3350.39 ; v2@4062.99,3330.71 v2@4062.99,3342.52 ; EXTHDR3.73@4062.99,3409.45 v2@4062.99,3342.52 ; v2@4094.49,3330.71 4094.49,3342.52 ; EXTHDR3.75@4094.49,3409.45 4094.49,3350.39 ; v2@4062.99,3342.52 4086.61,3342.52 4094.49,3342.52 ; 4094.49,3342.52 4094.49,3350.39
  Bottom Layer w7.87: R163.2@2637.8,3818.9 2598.43,3858.27 2598.43,4082.68 2681.1,4165.35 3114.17,4165.35 3228.35,4279.53 U30.5@3228.35,4307.45
  Bottom Layer w29.53: R163.2@2647.64,3812.99 2647.64,3631.89 2751.97,3527.56 3196.85,3527.56 3358.27,3366.14 3862.2,3366.14 3897.64,3330.71 v2(4059.06,3330.71) v2(4086.61,3330.71) v2(4114.17,3330.71)
PBPOWER.1V8PBA: EXTHDR1.77 EXTHDR1.79 R167.2 U34.5 | length 878
  Top Layer w19.68: EXTHDR1.79@763.78,3086.61 763.78,3007.87 ; EXTHDR1.77@795.28,3086.61 795.28,3007.87 ; v2@763.78,2992.13 v2(763.78,2980.32) v2(795.28,2980.32) v2@795.28,2992.13 ; v2@763.78,2992.13 763.78,3007.87 ; v2@763.78,2992.13 779.53,2992.13 v2@795.28,2992.13 ; 763.78,3007.87 v2(779.53,3007.87) 795.28,3007.87 ; v2@795.28,2992.13 795.28,3007.87
  Bottom Layer w7.87: R167.2@826.77,3090.55 824.8,3092.52 775.59,3141.73 775.59,3338.58 799.21,3362.2 822.83,3362.2 862.57,3401.94 U34.5@885.83,3401.94
  Bottom Layer w29.53: v2(763.78,2980.32) 779.53,2980.32 ; v2(795.28,2980.32) 779.53,2980.32 ; R167.2@826.77,3094.49 826.77,3090.55 826.77,3078.74 779.53,3031.5 v2(779.53,3007.87) 779.53,2980.32
PBPOWER.1V8PBB: EXTHDR2.77 EXTHDR2.79 R165.2 U32.5 | length 2449.8
  Top Layer w19.68: EXTHDR2.79@3244.09,3086.61 3244.09,3161.42 3244.09,3169.29 ; EXTHDR2.77@3275.59,3086.61 3275.59,3161.42 3275.59,3169.29 ; 3244.09,3169.29 v2(3244.09,3185.04) 3259.84,3185.04 v2(3275.59,3185.04) 3275.59,3169.29 ; 3244.09,3169.29 3259.84,3169.29 3275.59,3169.29
  Bottom Layer w7.87: R165.2@2332.68,3602.36 2330.71,3604.33 2283.46,3651.57 2283.46,3925.2 2618.11,4259.84 2763.78,4259.84 2785.43,4281.5 U32.5@2785.43,4307.45
  Bottom Layer w29.53: v2(3259.84,3161.42) 3259.84,3185.04 3259.84,3200.79 3196.85,3263.78 2829.22,3263.78 2723,3370 2513,3370 2332.68,3550.32 R165.2@2332.68,3602.36 ; R165.2@2332.68,3602.36 R165.2@2332.68,3606.3 R165.2@2332.68,3602.36
PBPOWER.1V8PBC: EXTHDR3.77 EXTHDR3.79 R166.2 U33.5 | length 3003.9
  Top Layer w19.68: EXTHDR3.77@4125.98,3409.45 4125.98,3476.38 ; EXTHDR3.79@4157.48,3409.45 4157.48,3476.38 ; 4125.98,3476.38 v2(4114.17,3488.19) v2(4141.73,3488.19) ; 4125.98,3476.38 4125.98,3488.19 v2(4141.73,3488.19) ; 4125.98,3476.38 4141.73,3476.38 4157.48,3476.38 ; v2(4141.73,3488.19) 4157.48,3488.19 4157.48,3476.38 ; v2(4141.73,3488.19) v2(4169.29,3488.19) 4157.48,3476.38
  Bottom Layer w7.87: R166.2@2838.58,3814.96 2795.28,3858.27 2795.28,4062.99 2834.65,4102.36 3346.46,4102.36 3523.62,4279.53 U33.5@3523.62,4307.45
  Bottom Layer w29.53: R166.2@2844.49,3812.99 2844.49,3698.82 2933.07,3610.24 4032.76,3610.24 4058,3585 4058,3488.19 v2(4114.17,3488.19) v2(4141.73,3488.19) v2(4169.29,3488.19)
PBPOWER.2V5PBA: EXTHDR1.81 EXTHDR1.83 R170.2 U37.5 | length 773.2
  Top Layer w19.68: EXTHDR1.83@700.79,3086.61 v2(700.79,3007.87) ; EXTHDR1.81@732.28,3086.61 v2(732.28,3007.87) ; v2(700.79,3007.87) 700.79,2996.06 v2(716.54,2980.32) ; v2(700.79,3007.87) 716.54,3007.87 ; v2(716.54,2980.32) 732.28,2996.06 v2(732.28,3007.87) ; v2(716.54,2980.32) 716.54,3007.87 ; 716.54,3007.87 v2(732.28,3007.87)
  Bottom Layer w7.87: R170.2@728.35,3090.55 726.38,3092.52 677.17,3141.73 677.17,3330.71 708.66,3362.2 728.35,3362.2 738.19,3372.05 U37.5@738.19,3401.94
  Bottom Layer w29.53: v2(716.54,2980.32) 716.54,3007.87 716.54,3031.5 728.35,3043.31 728.35,3090.55 R170.2@728.35,3094.49
PBPOWER.2V5PBB: EXTHDR2.81 EXTHDR2.83 R168.2 U35.5 | length 2348.7
  Top Layer w19.68: EXTHDR2.83@3181.1,3086.61 v2(3181.1,3161.42) ; EXTHDR2.81@3212.6,3086.61 v2(3212.6,3161.42) ; v2(3181.1,3161.42) 3181.1,3169.29 v2(3196.85,3185.04) 3212.6,3169.29 v2(3212.6,3161.42) ; v2(3181.1,3161.42) v2(3212.6,3161.42)
  Bottom Layer w7.87: R168.2@2236.22,3602.36 2233.27,3605.32 2185.04,3653.54 2185.04,3889.76 2204.72,3909.45 2220.47,3909.45 2618.47,4307.45 U35.5@2637.8,4307.45
  Bottom Layer w29.53: R168.2@2234.25,3606.3 2254,3586.55 2254,3545 2506,3293 2751.17,3293 2819.76,3224.41 3177.17,3224.41 3196.85,3204.72 v2(3196.85,3185.04)
PBPOWER.2V5PBC: EXTHDR3.81 EXTHDR3.83 R169.2 U36.5 | length 3151.9
  Top Layer w19.68: v2@4188.98,3330.71 4188.98,3342.52 ; EXTHDR3.81@4188.98,3409.45 4188.98,3342.52 ; v2@4220.47,3330.71 4220.47,3342.52 ; EXTHDR3.83@4220.47,3409.45 4220.47,3342.52 ; 4188.98,3342.52 v2(4177.17,3330.71) v2(4204.72,3330.71) v2(4232.28,3330.71) 4220.47,3342.52 ; 4188.98,3342.52 4204.72,3342.52 4220.47,3342.52
  Bottom Layer w7.87: R169.2@2740.16,3814.96 2696.85,3858.27 2696.85,4062.99 2767.72,4133.86 3228.35,4133.86 3375.98,4281.5 U36.5@3375.98,4307.45
  Bottom Layer w29.53: R169.2@2746.06,3812.99 2746.06,3596.46 2775.59,3566.93 3216.54,3566.93 3377.95,3405.51 3885.83,3405.51 3917.32,3374.02 4133.86,3374.02 v2(4177.17,3330.71) v2(4204.72,3330.71) v2(4232.28,3330.71)
PBPOWER.3V3PBA: EXTHDR1.85 EXTHDR1.87 R173.2 U40.5 | length 768.5
  Top Layer w19.68: EXTHDR1.87@637.79,3086.61 637.79,3007.87 637.79,3000 ; EXTHDR1.85@669.29,3086.61 669.29,3007.87 669.29,3000 ; 637.79,3000 v2(637.8,2980.32) v2(669.29,2980.32) 669.29,3000 ; 637.8,3000 653.54,3000 669.29,3000
  Bottom Layer w7.87: U40.5@590.55,3401.94 590.55,3370.08 578.74,3358.27 578.74,3141.73 627.95,3092.52 R173.2@629.92,3090.55
  Bottom Layer w29.53: R173.2@629.92,3094.49 629.92,3090.55 629.92,3047.24 653.54,3023.62 v2(653.54,3007.87) 653.54,2980.32 ; v2(637.8,2980.32) 653.54,2980.32 ; v2(669.29,2980.32) 653.54,2980.32
PBPOWER.3V3PBB: EXTHDR2.85 EXTHDR2.87 R171.2 U38.5 | length 2934
  Top Layer w19.68: EXTHDR2.87@3118.11,3086.61 3118.11,3161.42 v2@3118.11,3173.23 ; EXTHDR2.85@3149.61,3086.61 3149.61,3161.42 v2@3149.61,3173.23 ; v2@3118.11,3173.23 v2(3118.11,3185.04) 3133.86,3185.04 v2(3149.61,3185.04) v2@3149.61,3173.23 ; v2@3118.11,3173.23 3133.86,3173.23 v2@3149.61,3173.23
  Bottom Layer w7.87: R171.2@2031.5,3606.3 1980.32,3657.48 1980.32,3854.33 2098.43,3972.44 2188.98,3972.44 2342.52,4125.98 U38.5@2342.52,4307.45
  Bottom Layer w29.53: R171.2@2047.24,3606.3 2047.24,3192.91 2070.87,3169.29 2181.1,3169.29 2291.34,3059.06 2787.4,3059.06 2854.33,2992.13 2984.25,2992.13 3133.86,3141.73 v2(3133.86,3161.42) v2@3133.86,3169.29 ; v2@3133.86,3169.29 v2(3149.61,3185.04) 3133.86,3185.04 v2(3118.11,3185.04) v2@3133.86,3169.29
PBPOWER.3V3PBC: EXTHDR3.85 EXTHDR3.87 R172.2 U39.5 | length 3090.1
  Top Layer w19.68: 4251.97,3472.44 4250,3474.41 v2(4236.22,3488.19) v2(4263.78,3488.19) v2@4283.46,3488.19 ; EXTHDR3.85@4251.97,3409.45 4251.97,3476.38 ; v2@4251.97,3488.19 4251.97,3476.38 ; EXTHDR3.87@4283.47,3409.45 4283.47,3476.38 ; v2(4291.34,3488.19) v2@4283.46,3488.19 ; 4251.97,3476.38 4263.78,3476.38 4283.47,3476.38 ; 4283.47,3476.38 v2@4283.47,3488.19
  Bottom Layer w7.87: R172.2@2940.94,3811.02 2893.7,3858.27 2893.7,4047.24 2917.32,4070.87 3460.63,4070.87 3671.26,4281.5 U39.5@3671.26,4307.45
  Bottom Layer w29.53: R172.2@2942.91,3797.24 2893.7,3748.03 2893.7,3712.6 2948.82,3657.48 4189.52,3657.48 4236.22,3610.78 v2(4236.22,3488.19) v2(4263.78,3488.19) v2(4291.34,3488.19)
PBPOWER.5V0PBA: EXTHDR1.89 EXTHDR1.91 EXTHDR1.93 R176.2 U43.5 | length 1056.4
  Top Layer w19.68: v2(543.31,3007.87) EXTHDR1.93@543.31,3086.61 ; v2(574.8,3007.87) EXTHDR1.91@574.8,3086.61 ; v2(606.3,3007.87) EXTHDR1.89@606.3,3086.61
  Top Layer w25: v2(543.31,3007.87) v2(574.8,3007.87) v2(606.3,3007.87)
  Bottom Layer w7.87: U43.5@148.61,3400.9 148.61,3242.39 241.39,3149.61 476.38,3149.61 R176.2@531.5,3094.49
  Bottom Layer w29.53: R176.2@531.5,3094.49 531.5,3051.18 543.31,3039.37 v2(543.31,3007.87) v2(574.8,3007.87) v2(606.3,3007.87)
PBPOWER.5V0PBB: EXTHDR2.89 EXTHDR2.91 EXTHDR2.93 R174.2 U41.5 | length 2479.6
  Top Layer w19.68: EXTHDR2.93@3023.62,3086.61 v2(3023.62,3161.42) v2(3055.12,3161.42) ; EXTHDR2.91@3055.12,3086.61 v2(3055.12,3161.42) ; EXTHDR2.89@3086.61,3086.61 v2(3086.61,3161.42) v2(3055.12,3161.42)
  Bottom Layer w7.87: R174.2@2133.86,3604.33 2086.61,3651.57 2086.61,3913.39 2114.17,3940.94 2204.72,3940.94 2490.16,4226.38 U41.5@2490.16,4307.45
  Bottom Layer w29.53: R174.2@2135.83,3606.3 2308,3434.13 2308,3239 2334,3213 2759.44,3213 2799.21,3173.23 2921.26,3173.23 2933.07,3161.42 v2(3023.62,3161.42) v2(3055.12,3161.42) v2(3086.61,3161.42)
PBPOWER.5V0PBC: EXTHDR3.89 EXTHDR3.91 EXTHDR3.93 R175.2 U42.5 | length 3476.6
  Top Layer w19.68: v2@4314.96,3330.71 EXTHDR3.89@4314.96,3409.45 ; 4346.46,3330.71 EXTHDR3.91@4346.46,3409.45 ; 4377.95,3330.71 EXTHDR3.93@4377.95,3409.45
  Top Layer w29.53: v2(4267.72,3330.71) v2(4295.28,3330.71) 4314.96,3330.71 v2(4322.83,3330.71) 4377.95,3330.71
  Bottom Layer w7.87: R175.2@2547.24,3811.02 2496.06,3862.2 2496.06,4043.31 2649.61,4196.85 3000,4196.85 3080.71,4277.56 U42.5@3080.71,4307.45
  Bottom Layer w29.53: R175.2@2549.21,3812.99 2549.21,3671.26 2732.28,3488.19 3177.17,3488.19 3409.45,3255.91 4259.84,3255.91 4295.28,3291.34 v2(4295.28,3330.71) ; v2@4271.65,3330.71 v2(4295.28,3330.71) ; v2(4322.83,3330.71) v2(4295.28,3330.71)
PBSPI.DIN: EXTHDR1.55 EXTHDR2.55 EXTHDR3.55 U5.N5 | length 10120
  Top Layer w5: EXTHDR1.55@1141.73,3086.61 1141.73,3153.54 1185.19,3197 1212.45,3197 1220.47,3188.98 v1(1255.91,3188.98)
  Top Layer w7.87: v1(3622.05,3007.87) EXTHDR2.55@3622.05,3086.61 ; v1(3779.53,3330.71) EXTHDR3.55@3779.53,3409.45 ; v1(9633.86,3484.25) U5.N5@9653.54,3464.57
  MidLayer1 w5: v1(1255.91,3188.98) 1295.28,3188.98 1318.9,3165.36 1318.9,3149.61 1503.94,2964.57 2097.8,2964.57 2267.09,3133.86 2767.72,3133.86 2814.96,3181.1 2909.45,3181.1 3000,3090.55 3511.81,3090.55 3568.3,3034.07 3568.3,2998.63 3582.68,2984.25 3598.43,2984.25 v1(3622.05,3007.87) 3622.05,3102.36 3728.35,3208.66 3728.35,3346.46 3740.16,3358.27 3767.72,3358.27 3779.53,3346.46 v1(3779.53,3330.71)
  MidLayer2 w5: v1(3622.05,3007.87) 3665.35,2964.57 3796,2964.57 3909.86,3078.43 4400.28,3078.43 4466.9,3011.81 4854.33,3011.81 4940.95,3098.43 4940.95,3141.73 5220.47,3421.26 6031.5,3421.26 6366.14,3086.61 8355.05,3086.61 8607.02,3338.58 9094.49,3338.58 9220.47,3464.57 9413.39,3464.57 9433.07,3464.57 9614.17,3464.57 v1(9633.86,3484.25)
PBSPI.DOUT: EXTHDR1.53 EXTHDR2.53 EXTHDR3.53 U5.M8 | length 10091.8
  Top Layer w5: EXTHDR1.53@1173.23,3086.61 1173.23,3153.54 1177.16,3157.48 1216.54,3157.48 1224.41,3165.36 v1(1283.46,3165.36)
  Top Layer w7.87: v1(3653.54,3007.87) EXTHDR2.53@3653.54,3086.61 ; v1(3748.03,3330.71) EXTHDR3.53@3748.03,3409.45 ; v1(9751.97,3523.62) U5.M8@9771.65,3503.94
  MidLayer1 w5: v1(1283.46,3165.36) 1496.06,2952.76 2107.72,2952.76 2277.01,3122.05 2775.59,3122.05 2822.83,3169.29 2901.58,3169.29 2992.13,3078.74 3503.94,3078.74 3555.12,3027.56 3555.12,2992.13 3578.74,2968.5 3614.18,2968.5 v1(3653.54,3007.87) 3653.54,3118.11 3748.03,3212.6 v1(3748.03,3330.71)
  MidLayer2 w5: v1(3653.54,3007.87) 3685.04,2976.38 3793.67,2976.38 3905.72,3088.43 4404.43,3088.43 4469.23,3023.62 4846.46,3023.62 4929.13,3106.3 4929.13,3149.61 5212.6,3433.07 6035.43,3433.07 6370.08,3098.43 8350.16,3098.43 8602.13,3350.39 9090.55,3350.39 9244.1,3503.94 9732.28,3503.94 v1(9751.97,3523.62)
PBSPI.SCLK: EXTHDR1.57 EXTHDR2.57 EXTHDR3.57 U5.P5 | length 10196.3
  Top Layer w5: EXTHDR1.57@1110.24,3086.61 1110.24,3141.24 1179,3210 v1(1230,3210)
  Top Layer w7.87: v1(3590.55,3007.87) EXTHDR2.57@3590.55,3086.61 ; v1(3811.02,3330.71) EXTHDR3.57@3811.02,3409.45 ; v1(9633.86,3405.51) U5.P5@9653.54,3425.2
  MidLayer1 w5: v1(1230,3210) 1293.94,3210 1330.71,3173.23 1330.71,3157.48 1511.81,2976.38 2089.61,2976.38 2258.9,3145.67 2759.84,3145.67 2807.09,3192.91 2917.32,3192.91 3007.87,3102.36 3519.69,3102.36 3590.55,3031.5 v1(3590.55,3007.87) 3606.3,3023.62 3606.3,3102.36 3716.54,3212.6 3716.54,3358.27 3728.35,3370.08 3791.34,3370.08 3811.02,3350.39 v1(3811.02,3330.71)
  MidLayer2 w5: v1(3590.55,3007.87) 3645.67,2952.76 3798.33,2952.76 3914,3068.43 4396.14,3068.43 4464.57,3000 4866.14,3000 4952.76,3086.61 4952.76,3133.86 5228.35,3409.45 6027.56,3409.45 6362.2,3074.8 8359.95,3074.8 8611.92,3326.77 9098.43,3326.77 9196.85,3425.2 9413.39,3425.2 9433.07,3425.2 9614.17,3425.2 v1(9633.86,3405.51)
PDA.D0: HDR_B1.42 U5.R8 | length 4529.5
  Top Layer w5: v1(7118.11,1456.69) HDR_B1.42@7118.11,1531.5
  Top Layer w7.87: v1(9751.97,3366.14) U5.R8@9771.65,3385.83
  MidLayer2 w5: v9(9149.5,3247.9) 9149.5,3312.5 9222.83,3385.83 9460.63,3385.83 ; 9433.07,3385.83 9732.28,3385.83 v1(9751.97,3366.14)
  MidLayer4 w5: v1(7118.11,1456.69) 7118.11,1591.11 7132,1605 7728,1605 8001,1878 8661,1878 8771,1988 8771,2663 8675,2759 8675,2944 8734,3003 8898.9,3003 8913.6,3017.7 8913.6,3241.7 8937.49,3265.59 9131.81,3265.59 v9(9149.5,3247.9)
PDA.D1: HDR_B1.44 U5.E7 | length 5834.7
  Top Layer w5: v1(7149.61,1456.69) HDR_B1.44@7149.61,1531.5
  Top Layer w7.87: v1(9712.6,3799.21) U5.E7@9732.28,3779.53
  MidLayer2 w5: v8(9327,4358) 9354,4385 9412.4,4385 9452.4,4345 9555.35,4345 9693,4207.35 9693,3818.81 v1(9712.6,3799.21)
  MidLayer4 w5: v1(7149.61,1456.69) 7149.61,1573.61 7171,1595 7732.14,1595 8005.14,1868 8665.14,1868 8781,1983.86 8781,2667.14 8685,2763.14 8685,2939.86 8738.14,2993 8854,2993 v9(8867,2980)
  Bottom Layer w5: v9(8867,2980) 8885.86,2980 8892.86,2987 9169.52,2987 9191.3,3008.78 9191.3,4162.58 9327,4298.28 v8(9327,4358)
PDA.D2: HDR_B1.46 U5.E6 | length 5732.9
  Top Layer w5: v1(7181.1,1456.69) HDR_B1.46@7181.1,1531.5
  Top Layer w7.87: v1(9673.23,3799.21) U5.E6@9692.91,3779.53
  MidLayer2 w5: v8(9365.5,4347.2) 9382.8,4347.2 9405,4325 9547.07,4325 9653.46,4218.61 9653.46,3828.7 9673.23,3808.93 v1(9673.23,3799.21)
  MidLayer4 w5: v1(7181.1,1456.69) 7181.1,1563 7203.1,1585 7736.28,1585 8009.28,1858 8669.28,1858 8791,1979.72 8791,2671.28 8695,2767.28 8695,2935.72 8742.28,2983 8812,2983 v9(8850,2945)
  Bottom Layer w5: v9(8850,2945) 8865,2945 8897,2977 9173.66,2977 9201.3,3004.64 9201.3,4158.44 9347,4304.14 9347,4328.7 v8(9365.5,4347.2)
PDA.D3: HDR_B1.48 U5.C6 | length 5657.4
  Top Layer w5: v1(7212.6,1456.69) HDR_B1.48@7212.6,1531.5
  Top Layer w7.87: v1(9673.23,3877.95) U5.C6@9692.91,3858.27
  MidLayer2 w5: v8(9405,4358) 9428,4335 9551.21,4335 9673.23,4212.98 v1(9673.23,3877.95)
  MidLayer4 w5: v1(7212.6,1456.69) 7212.6,1557 7230.6,1575 7740.43,1575 8013.43,1848 8673.43,1848 8801,1975.57 8801,2675.43 8705,2771.43 8705,2931.57 8733.43,2960 v9(8778,2960)
  Bottom Layer w5: v9(8778,2960) 8811.7,2960 8855.2,3003.5 8877.1,3003.5 8883.6,2997 9165.37,2997 9181.3,3012.93 9181.3,4166.73 9297.5,4282.93 9297.5,4358.5 9317.8,4378.8 9384.2,4378.8 v8(9405,4358)
PDA.D4: HDR_B1.50 U5.H11 | length 5948.5
  Top Layer w5: v1(7244.09,1456.69) HDR_B1.50@7244.09,1531.5
  Top Layer w7.87: v1(9870.08,3681.1) U5.H11@9889.76,3661.42
  MidLayer2 w5: v8(9372,4315) 9542.93,4315 9643.46,4214.47 9643.46,3972.46 9614,3943 9614,3825 9620.3,3818.7 9644.2,3818.7 9653.8,3809.1 9653.8,3784.2 9658.47,3779.53 9842.47,3779.53 9850.39,3771.61 9850.39,3700.79 v1(9870.08,3681.1)
  MidLayer4 w5: v1(7244.09,1456.69) 7244.09,1545 7264.09,1565 7744.57,1565 8017.57,1838 8677.57,1838 8811,1971.43 8811,2679.57 8715,2775.57 8715,2927.43 8725.97,2938.4 8822.5,2938.4 8837.5,2923.4 8877.4,2923.4 v9(8894,2940)
  Bottom Layer w5: v9(8894,2940) 8894,2959.86 8901.14,2967 9177.8,2967 9211.3,3000.5 9211.3,4154.3 v8(9372,4315)
PPRT#.ACK: HDR6.10 R24.1 | length 260.2
  Bottom Layer w5: R24.1@1011.81,5781.02 1011.81,5840.55 1063.78,5892.52 HDR6.10@1063.78,6019.69
PPRT#.AUTOFD: HDR6.14 R35.2 | length 591.6
  Bottom Layer w5: HDR6.14@1963.78,6119.69 2030.37,6053.1 2030.37,5967.24 2153.94,5843.67 2175.73,5843.67 2224,5795.4 2224,5773.1 2211.6,5760.7 2134.5,5760.7 R35.2@2114.17,5781.02
  Bottom Layer w7.87: R35.2@2114.17,5779.92 R35.2@2114.17,5781.02
PPRT#.BUSY: HDR6.11 R23.1 | length 251.4
  Bottom Layer w5: R23.1@933.07,5781.02 933.07,5840.55 963.78,5871.26 HDR6.11@963.78,6019.69
PPRT#.D0: HDR6.2 R32.2 | length 314.8
  Bottom Layer w5: HDR6.2@1863.78,6019.69 1863.78,5978.74 2035.43,5807.09 R32.2@2035.43,5781.02
  Bottom Layer w7.87: R32.2@2035.43,5775.99 R32.2@2035.43,5781.02
PPRT#.D1: HDR6.3 R31.2 | length 253.3
  Bottom Layer w5: HDR6.3@1763.78,6019.69 1763.78,5875.98 1799.21,5840.55 R31.2@1799.21,5781.02
PPRT#.D2: HDR6.4 R30.2 | length 247.8
  Bottom Layer w7.87: R30.2@1641.73,5781.02 1641.73,5840.55 1663.78,5862.6 HDR6.4@1663.78,6019.69
PPRT#.D3: HDR6.5 R29.2 | length 304.2
  Bottom Layer w5: R29.2@1405.51,5781.02 1405.51,5861.42 HDR6.5@1563.78,6019.69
